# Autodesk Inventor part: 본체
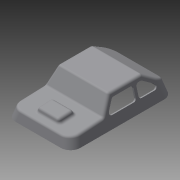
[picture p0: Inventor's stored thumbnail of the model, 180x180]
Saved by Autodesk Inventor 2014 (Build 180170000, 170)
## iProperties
Created: 2015-05
Part Number: 본체
Material: 일반
Document SubType Name: Modeling
Designer: net
Density: 1 g/cm^3
Appearance: 기본값
Author: net
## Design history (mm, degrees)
sketch "스케치1"
  geometry: L1 (0, 0)-(-76, 0); L2 (-76, 0)-(-67.694, 31); L3 (-67.694, 31)-(-8.306, 31); L4 (-8.306, 31)-(0, 0)
  constraints: 8 end point, 1 horizontal, 1 parallel
  dimensions: "d0" = 76 distance of L1.start L1.end; "d1" = 105 deg angle of L1 L2; "d2" = 105 deg angle of L1 L4; "d3" = 31 distance between parallel lines of L1 L3
extrude "돌출1" new body sketch "스케치1" distance "d4" = 122; taper "d5" = 0 deg
node "작업 평면1"
sketch "스케치2"
  geometry: L1 (0, 31)-(0, 0) reference; L2 (0, 31)-(122, 31) reference; L3 (122, 0)-(122, 31) reference; L4 (0, 0)-(122, 0) reference; L5 (0, 0)-(2.978, 11.113); L6 (2.978, 11.113)-(42, 13.158); L7 (42, 13.158)-(53.149, 31); L8 (92, 31)-(118.412, 13.392); L9 (118.412, 13.392)-(122, 0); 1 further point
  constraints: 10 end point, 2 point on line
  dimensions: "d7" = 105 deg angle of L4 L5; "d8" = 3 deg angle of L4 L6; "d9" = 125 deg angle of L6 L7; "d10" = 42 horizontal distance of L6.end point (0, 0); "d11" = 30 horizontal distance of L3.start L8.start; "d38" = 105 deg angle of L4 L9
extrude "돌출2" cut sketch "스케치2" stored distance "d13" = 122; taper "d14" = 0 deg
sketch "스케치3"
  geometry: L1 (-13.865, 118.412)-(-32.094, 92) reference; L2 (-32.094, 53.149)-(-32.094, 92) reference; L3 (-32.094, 53.149)-(-13.622, 42) reference; L4 (-13.865, 118.412)-(-32.094, 92) reference; L5 (-32.094, 53.149)-(-32.094, 92) reference; L6 (-32.094, 53.149)-(-13.622, 42) reference; L7 (-13.622, 42)-(-11.505, 2.978) reference; L8 (-11.505, 2.978)-(0, 0) reference; L9 (0, 0)-(0, 122) reference; L10 (0, 122)-(-13.865, 118.412) reference; L11 (-12.094, 46.917)-(-12.094, 80.917); L12 (-12.094, 80.917)-(-27.094, 80.917); L13 (-27.094, 80.917)-(-27.094, 55.971); L14 (-27.094, 55.971)-(-12.094, 46.917); L15 (-12.094, 84.175)-(-12.094, 112.175); L16 (-12.094, 112.175)-(-27.094, 90.442); L17 (-27.094, 84.175)-(-12.094, 84.175); L18 (-27.094, 84.175)-(-27.094, 90.442); 1 further point
  constraints: 16 end point, 5 parallel, 3 perpendicular, 1 vertical alignment
  dimensions: "d15" = 5 distance between parallel lines of L2 L13; "d16" = 5 distance between parallel lines of L14 L3; "d17" = 34 distance of L11.start L11.end; "d18" = 15 distance between parallel lines of L11 L13; "d19" = 5 distance between parallel lines of L1 L16; "d20" = 28 distance of L15.start L15.end; "d21" = 15 distance between parallel lines of L15 L18
  node "투영된 루프2"
feature "쉘1" dims "d22" = 2
extrude "돌출3" cut sketch "스케치3" distance "d23" = 5; taper "d24" = 0 deg
fillet "모깎기1" dims "d25" = 3
sketch "스케치4"
  geometry: L1 (0, 0)-(70.045, 0) reference; L2 (22.022, 27.445)-(48.022, 27.445); L3 (48.022, 27.445)-(48.022, 7.445); L4 (48.022, 7.445)-(22.022, 7.445); L5 (22.022, 7.445)-(22.022, 27.445); L6 (-2.978, -3.555)-(73.022, -3.555) reference; 2 further points
  constraints: 8 end point, 2 midpoint, 2 parallel, 1 horizontal, 1 perpendicular, 1 vertical alignment
  dimensions: "d26" = 26 distance of L2.start L2.end; "d27" = 20 distance of L4.end L2.start; "d28" = 11 distance between parallel lines of L6 L4
extrude "돌출4" join sketch "스케치4" distance "d29" = 5; taper "d30" = 0 deg
sketch "스케치5"
  geometry: L1 (0, 20)-(-5, 20) reference; L2 (-5, 0)-(-5, 20) reference; L3 (0, 0)-(-5, 0) reference; L4 (10.942, -11)-(17.327, 110.833) reference; L5 (0, -7.445)-(0, 31.631) reference; L6 (0, 0)-(-5, 1.82); L7 (0, 20)-(-5, 18.18)
  constraints: 4 end point, 2 point on line
extrude "돌출5" cut sketch "스케치5" stored distance "d34" = 5; taper "d35" = 0 deg
fillet "모깎기2" dims "d36" = 3
fillet "모깎기3" dims "d37" = 3
fillet "모깎기4" dims "d39" = 3
fillet "모깎기5" dims "d40" = 12
fillet "모깎기6" dims "d41" = 12
node "솔리드1"
mirror "대칭1"
node "투영된 루프1"
other parameters: "d6" = 38
